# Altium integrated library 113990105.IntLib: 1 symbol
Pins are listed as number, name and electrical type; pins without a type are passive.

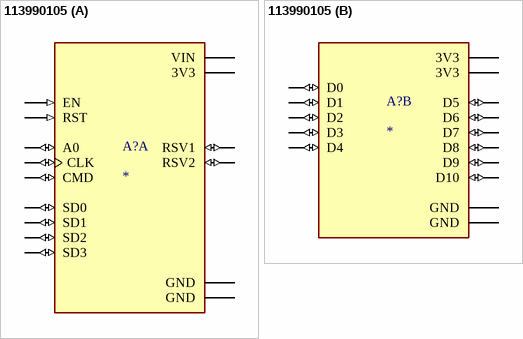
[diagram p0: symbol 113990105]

## 113990105
designator A?
NodeMCU v2 - Lua based ESP8266 development kit; MP: 113990105
footprint SEEED_113990105
part A pins: J1_1 A0 (io), J1_2 RSV1 (io), J1_3 RSV2 (io), J1_4 SD3 (io), J1_5 SD2 (io), J1_6 SD1 (io), J1_7 CMD (io), J1_8 SD0 (io), J1_9 CLK (io), J1_10 GND (power), J1_11 3V3 (power), J1_12 EN (in), J1_13 RST (in), J1_14 GND (power), J1_15 VIN (power)
part B pins: J2_1 D0 (io), J2_2 D1 (io), J2_3 D2 (io), J2_4 D3 (io), J2_5 D4 (io), J2_6 3V3 (power), J2_7 GND (power), J2_8 D5 (io), J2_9 D6 (io), J2_10 D7 (io), J2_11 D8 (io), J2_12 D9 (io), J2_13 D10 (io), J2_14 GND (power), J2_15 3V3 (power)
